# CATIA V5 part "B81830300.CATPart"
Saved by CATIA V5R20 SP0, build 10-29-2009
Part number: B81830300
Revision: 3
Definition: design
Nomenclature: B81830300
Source: made
Description: NOT SPECIFIED
Bounding box of the stored display mesh (mm): x -17.817 to 17.817, y -18 to 18, z 0 to 300
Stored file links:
  C:\Users\Raffaele\Desktop\3D X SITO CF\BOLEX\6-PILLAR REF 818\B81830300.CATPart
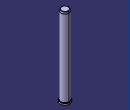
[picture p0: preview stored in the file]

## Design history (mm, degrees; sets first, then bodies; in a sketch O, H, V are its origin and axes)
Body1 "MANIFOLD_SOLID_BREP #370" (main body)
  Solid1: solid without history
